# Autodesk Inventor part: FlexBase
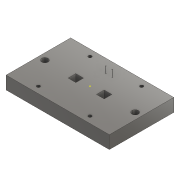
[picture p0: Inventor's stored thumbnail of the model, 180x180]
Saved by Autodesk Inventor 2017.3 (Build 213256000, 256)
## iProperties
Part Number: FlexBase
Material: ステンレス鋼
Document SubType Name: モデリング
Designer: kyushu-hep
Density: 8 g/cm^3
Appearance: 半つや出し
Sheet Metal Rule: Default
Mass: 5352.02 g
Surface Area: 367.335 cm^2
Volume: 277.307 cm^3
Author: kyushu-hep
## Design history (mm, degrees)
sketch "スケッチ1"
  geometry: L1 (-112, 0)-(112, 0) reference; L2 (0, -70)-(0, 70) reference; L3 (80, -50)-(-80, -50); L4 (-80, -50)-(-80, 50); L5 (-80, 50)-(80, 50); L6 (80, 50)-(80, -50); L7 (80, -50)-(-80, 50); L8 (-80, -50)-(80, 50); 1 further point
  constraints: 12 end point, 2 midpoint, 2 parallel, 1 horizontal, 1 perpendicular
  dimensions: "d0" = 160 distance of L4.end L5.end; "d1" = 100 distance of L3.end L4.end
extrude "押し出し1" new body sketch "スケッチ1" distance "d2" = 20; taper "d3" = 0 deg
sketch "スケッチ12"
  geometry: L1 (-80, 50)-(-80, -50) reference; L2 (-80, -50)-(80, -50) reference; C1 r 0.5 at (-5.05, 29.5); C2 r 0.5 at (5.05, 29.5); 1 further point
  constraints: 2 centre point
  dimensions: "d66" = 1 diameter of C1; "d67" = 1 diameter of C2; "d130" = 10.1 distance of C2.centre C1.centre; "d133" = 29.5 vertical distance of point (0, 0) C2.centre; "d134" = 5.05 horizontal distance of C1.centre point (0, 0)
extrude "押し出し9" join sketch "スケッチ12" distance "d72" = 10; taper "d73" = 0 deg
sketch "スケッチ18"
  geometry: L1 (-80, 50)-(-80, -50) reference; L2 (-16, -6)-(-28, -6); L3 (-28, -6)-(-28, 6); L4 (-28, 6)-(-16, 6); L5 (-16, 6)-(-16, -6); L6 (-16, -6)-(-28, 6); L7 (-28, -6)-(-16, 6); L8 (80, -50)-(80, 50) reference; L9 (16, -6)-(28, -6); L10 (28, -6)-(28, 6); L11 (28, 6)-(16, 6); L12 (16, 6)-(16, -6); L13 (16, -6)-(28, 6); L14 (28, -6)-(16, 6); L15 (-80, -50)-(80, -50) reference; 3 further points
  constraints: 24 end point, 4 midpoint, 4 parallel, 2 equal length, 2 horizontal, 2 perpendicular, 1 collinear
  dimensions: "d108" = 16 distance from line of point (0, 0) L5; "d109" = 12 distance of L4.end L2.start; "d135" = 6 distance from line of point (0, 0) L2; "d151" = 12 distance of L2.start L2.end; "d152" = 16 distance from line of L12 point (0, 0)
extrude "押し出し15" cut sketch "スケッチ18" distance "d111" = 30; taper "d112" = 0 deg
sketch "スケッチ22"
  geometry: 1 further point
sketch "スケッチ23"
  geometry: C1 r 5 at (-70, 0); C2 r 5 at (70, 0); 1 further point
  constraints: 2 centre point
  dimensions: "d153" = 10 diameter of C1; "d154" = 10 diameter of C2; "d155" = 70 distance of point (0, 0) C1.centre; "d156" = 70 distance of point (0, 0) C2.centre
extrude "押し出し18" cut sketch "スケッチ23" distance "d157" = 10; taper "d158" = 0 deg
sketch "スケッチ24"
  geometry: C1 r 2.5 at (-40, 40); C2 r 2.5 at (40, 40); C3 r 2.5 at (-40, -40); C4 r 2.5 at (40, -40); 2 further points
  constraints: 4 centre point
  dimensions: "d159" = 5 diameter of C1; "d160" = 40 horizontal distance of C1.centre point (0, 0); "d161" = 40 horizontal distance of C1.centre point (0, 0); "d162" = 5 diameter of C2; "d163" = 40 horizontal distance of point (0, 0) C2.centre; "d164" = 40 horizontal distance of C2.centre point (0, 0); "d165" = 5 diameter of C3; "d166" = 40 horizontal distance of point (0, 0) C3.centre; "d167" = 40 horizontal distance of point (0, 0) C3.centre; "d168" = 5 diameter of C4; "d169" = 40 horizontal distance of point (0, 0) C4.centre; "d170" = 40 horizontal distance of point (0, 0) C4.centre
extrude "押し出し19" cut sketch "スケッチ24" distance "d171" = 20; taper "d172" = 0 deg
feature "ねじ4" dims "d173" = 10, "d174" = 0
feature "ねじ5" dims "d175" = 10, "d176" = 0
feature "ねじ6" dims "d177" = 10, "d178" = 0
feature "ねじ7" dims "d179" = 10, "d180" = 0
node "ソリッド1"
other parameters: "Thickness" = 0.5, "Kファクター" = 4.4, "BendRadius" = 0.5 (= Thickness), "BendReliefWidth" = 0.5 (= Thickness), "BendReliefDepth" = 0.25 (= 0.5 x Thickness), "CornerReliefSize" = 2 (= 4 x Thickness), "SeamGap" = 0.01, "MinimumRemnant" = 1 (= 2 x Thickness), "TransitionRadius" = 0.5 (= BendRadius), "JacobiRadiusSize" = 0.5 (= Thickness), "GapSize" = 0.5 (= Thickness)
